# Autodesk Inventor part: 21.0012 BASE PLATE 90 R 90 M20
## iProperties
Created: 2009-01
Part Number: 21.0012 BASE PLATE 90 R 90 M20
Document SubType Name: Modeling
Designer: Administrator
Density: 1 g/cm^3
Author: Administrator
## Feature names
1. Base1
2. Extrusion1
